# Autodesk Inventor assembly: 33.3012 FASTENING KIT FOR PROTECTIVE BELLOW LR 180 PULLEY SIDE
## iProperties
Created: 2007-06
Part Number: 33.3012 FASTENING KIT FOR PROTECTIVE BELLOW LR 180 PULLEY SIDE
Document SubType Name: Assembly
Designer: Andy Moles
Author: Andy Moles
